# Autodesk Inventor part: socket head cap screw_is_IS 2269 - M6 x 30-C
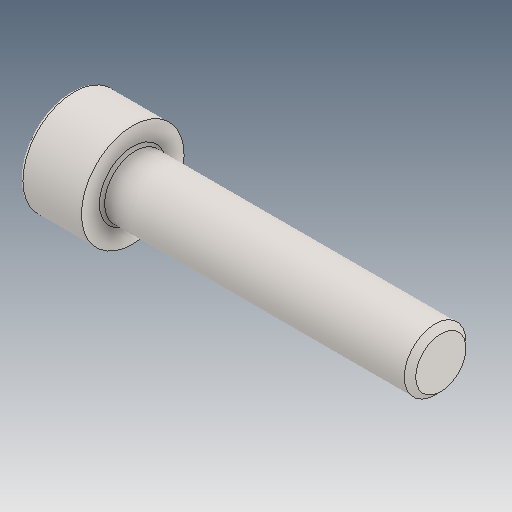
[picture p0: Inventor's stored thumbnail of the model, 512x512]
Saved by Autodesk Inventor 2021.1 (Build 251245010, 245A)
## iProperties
Created: 2021-05
Part Number: socket head cap screw_is_IS 2269 - M6 x 30-C
Material: Ogólny
Document SubType Name: Modeling
Designer: user
Density: 1 g/cm^3
Appearance: Domyślna
Author: user
Revision Number: ÈÎºÎ
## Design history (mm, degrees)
feature "ÊäÈë1"
node "Bryła1"
